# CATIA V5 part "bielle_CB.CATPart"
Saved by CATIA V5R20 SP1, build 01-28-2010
Part number: bielle_CB
Bounding box of the stored display mesh (mm): x -25.428 to 4.994, y 0 to 10, z -4.999 to 19.403
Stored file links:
  C:\Users\Matthieu\Desktop\IAO_2012_mcamard_Catia\bielle_CB.CATPart
  C:\Users\Matthieu\Desktop\IAO_Artobolevsky\Artobolevsky_786.CATProduct
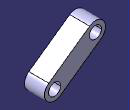
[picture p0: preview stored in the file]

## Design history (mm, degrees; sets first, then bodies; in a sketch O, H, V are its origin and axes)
Set1
  Plane1: linked copy from another document
  Point1 "C": linked copy from another document
  Point2 "B": linked copy from another document
Body1 (main body)
  Sketch1 on Plane1, origin (0, 0, 0), H (-1, 0, 0), V (0, 0, 1)
    construction line L1 (0, 0) -> (20.4337, 14.4036)
    point P1 (0, 0)
    point P2 (20.4337, 14.4036)
    line L2 (-2.8807, 4.0867) -> (17.553, 18.4903)
    line L3 (23.3144, 10.3168) -> (2.8807, -4.0867)
    arc A1 centre (20.4337, 14.4036) radius 5 from (17.553, 18.4903) to (23.3144, 10.3168) cw
    arc A2 centre (0, 0) radius 5 from (2.8807, -4.0867) to (-2.8807, 4.0867) cw
    circle A3 centre (20.4337, 14.4036) radius 3
    circle A4 centre (0, 0) radius 3
    reference projected point E1 (0, 0) from Point1
    reference projected point E2 (20.4337, 14.4036) from Point2
    distance L1 L2 = 5
    tangency: A1 L2, A2 L2, A1 L3, A2 L3
    coincidence: P1 E1, P2 E2
  Pad1: profile Sketch1, direction (0, 1, 0), length 10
